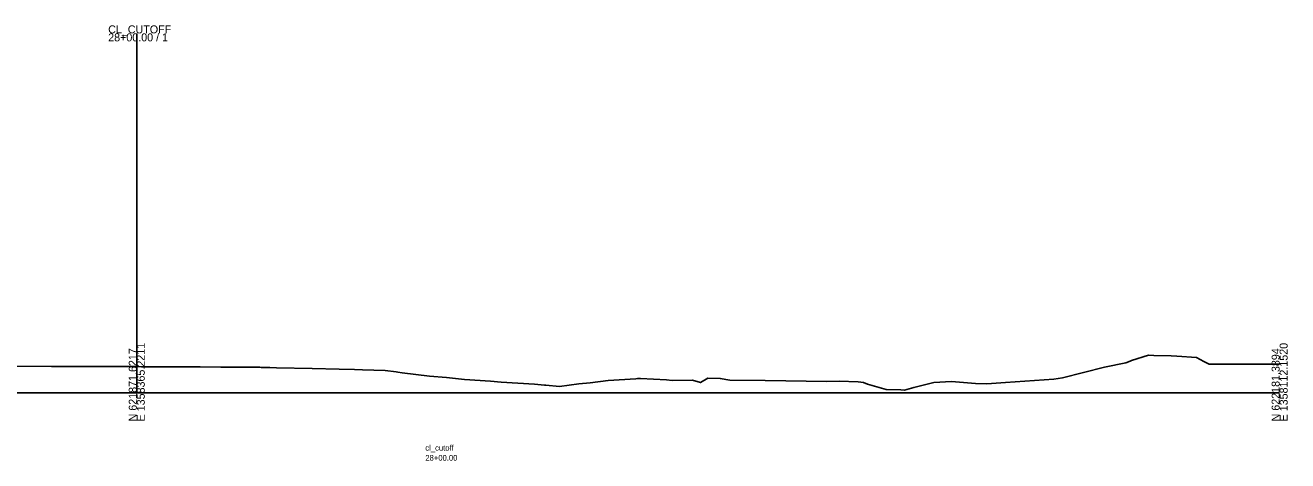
# Model space of a CAD drawing. Extents: x -26 to 803, y -24 to 2573.
# Drawn here: x 361 to 802.8, y -23.8 to 128.7 of the extents above; entities that cross this region are included whole.
import ezdxf

# ---------------------------------------------------------------- set-up
doc = ezdxf.new("R2010")
doc.units = 0
for name, color, linetype in [('DESIGN - SHEET - Light Grid', 7, 'Continuous'), ('DESIGN - TYPICAL - Warning Text', 7, 'Continuous'), ('SURVEY - GROUND - Top of Ground', 7, 'Continuous')]:
    doc.layers.add(name, color=color, linetype=linetype)

msp = doc.modelspace()

# ---------------------------------------------------------------- linework, layer by layer
at = {"layer": 'DESIGN - SHEET - Light Grid'}
for p, q in [((400, 0), (400, 125.84)), ((0, 0), (400, 0)), ((400, 0), (800, 0))]:
    msp.add_line(p, q, dxfattribs=at)
at = {"layer": 'SURVEY - GROUND - Top of Ground'}
msp.add_lwpolyline([(357.39, 9.31), (370.16, 9.26), (379.33, 9.24), (385.37, 9.22), (396.93, 9.21), (400, 9.21), (400.46, 9.21), (401.64, 9.16), (414.92, 9.11), (422.16, 9.07), (429.46, 9.03), (443.05, 8.93), (443.53, 8.91), (443.93, 8.91), (446.6, 8.84), (448.85, 8.78), (461.4, 8.52), (470.79, 8.26), (476.18, 8.14), (479.02, 8.06), (486.98, 7.82), (490.74, 7.3), (491.35, 7.25), (492.93, 7.05), (502.46, 5.82), (508.42, 5.4), (514.69, 4.69), (523.84, 4.1), (527.52, 3.73), (539.21, 3.05), (542.69, 2.7), (543.22, 2.66), (547.91, 2.18), (554.77, 3.17), (558.74, 3.52), (564.95, 4.28), (574.63, 4.92), (575.23, 4.99), (576.34, 5.04), (585.37, 4.55), (587.39, 4.36), (594.49, 4.46), (597.26, 3.61), (599.88, 5.15), (604.23, 5.06), (607.61, 4.47), (619.94, 4.37), (641.51, 3.96), (645.78, 4.04), (652.48, 3.82), (654.36, 3.66), (655.78, 3.06), (662.33, 1.19), (667.38, 1.05), (668.73, 0.99), (671.96, 1.84), (678.98, 3.62), (685.16, 3.95), (693.51, 3.26), (697.54, 3.13), (704.09, 3.56), (720.92, 4.83), (724.01, 5.27), (738.7, 8.95), (746.18, 10.52), (747.65, 11.07), (748.17, 11.34), (754.07, 13.21), (755.95, 13.12), (762.05, 12.93), (763.97, 12.8), (770.92, 12.34), (773.46, 10.98), (775.39, 10.04), (779.58, 10.04), (781.83, 10.04), (791.08, 10.04), (798.6, 10.04), (800, 10.04)], dxfattribs=at)

# ---------------------------------------------------------------- texts
at = {"layer": 'DESIGN - SHEET - Light Grid'}
for s, p in [('CL_CUTOFF', (390, 125.84)), ('28+00.00 / 1', (390, 123.04))]:
    msp.add_text(s, height=2.8, dxfattribs=at).set_placement(p)
for s, p in [('N 621871.6217', (400, -10)), ('E 1358365.2211', (402.8, -10)), ('N 622181.3894', (800, -10)), ('E 1358112.1520', (802.8, -10))]:
    msp.add_text(s, height=2.8, rotation=90, dxfattribs=at).set_placement(p)
at = {"layer": 'DESIGN - TYPICAL - Warning Text'}
for s, p in [('cl_cutoff', (501, -20.25)), ('28+00.00', (501, -23.75))]:
    msp.add_text(s, height=2, dxfattribs=at).set_placement(p)

doc.saveas('drawing.dxf')
